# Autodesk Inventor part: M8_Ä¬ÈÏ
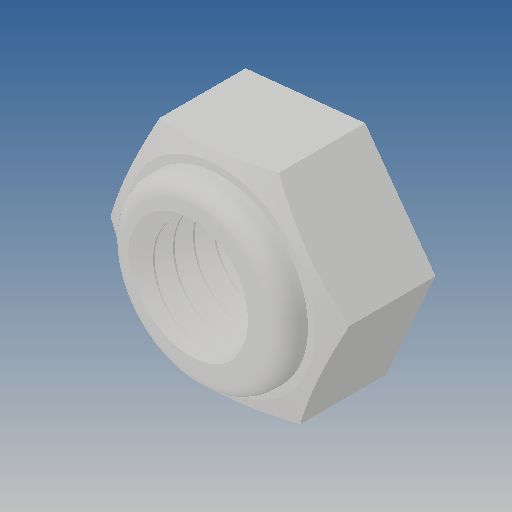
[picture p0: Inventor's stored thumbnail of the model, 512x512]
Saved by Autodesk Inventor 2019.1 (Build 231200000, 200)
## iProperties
Created: 2010-06
Part Number: M8_Ä¬ÈÏ
Material: Ogólny
Document SubType Name: Modeling
Designer: CADENGINEERING4
Density: 1 g/cm^3
Appearance: Domyślna
Author: CADENGINEERING4
Revision Number: ÈÎºÎ
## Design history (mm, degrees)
feature "NONE"
node "Bryła1"
